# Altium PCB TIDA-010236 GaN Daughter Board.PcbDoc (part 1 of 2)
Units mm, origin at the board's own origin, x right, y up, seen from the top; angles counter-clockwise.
Board outline 68 x 45 mm, 4 copper layers (Top Layer, Signal Layer 1, Signal Layer 2, Bottom Layer), stack 1.57 mm thick; 74 components, 38 nets, 269 pads, 167 vias.
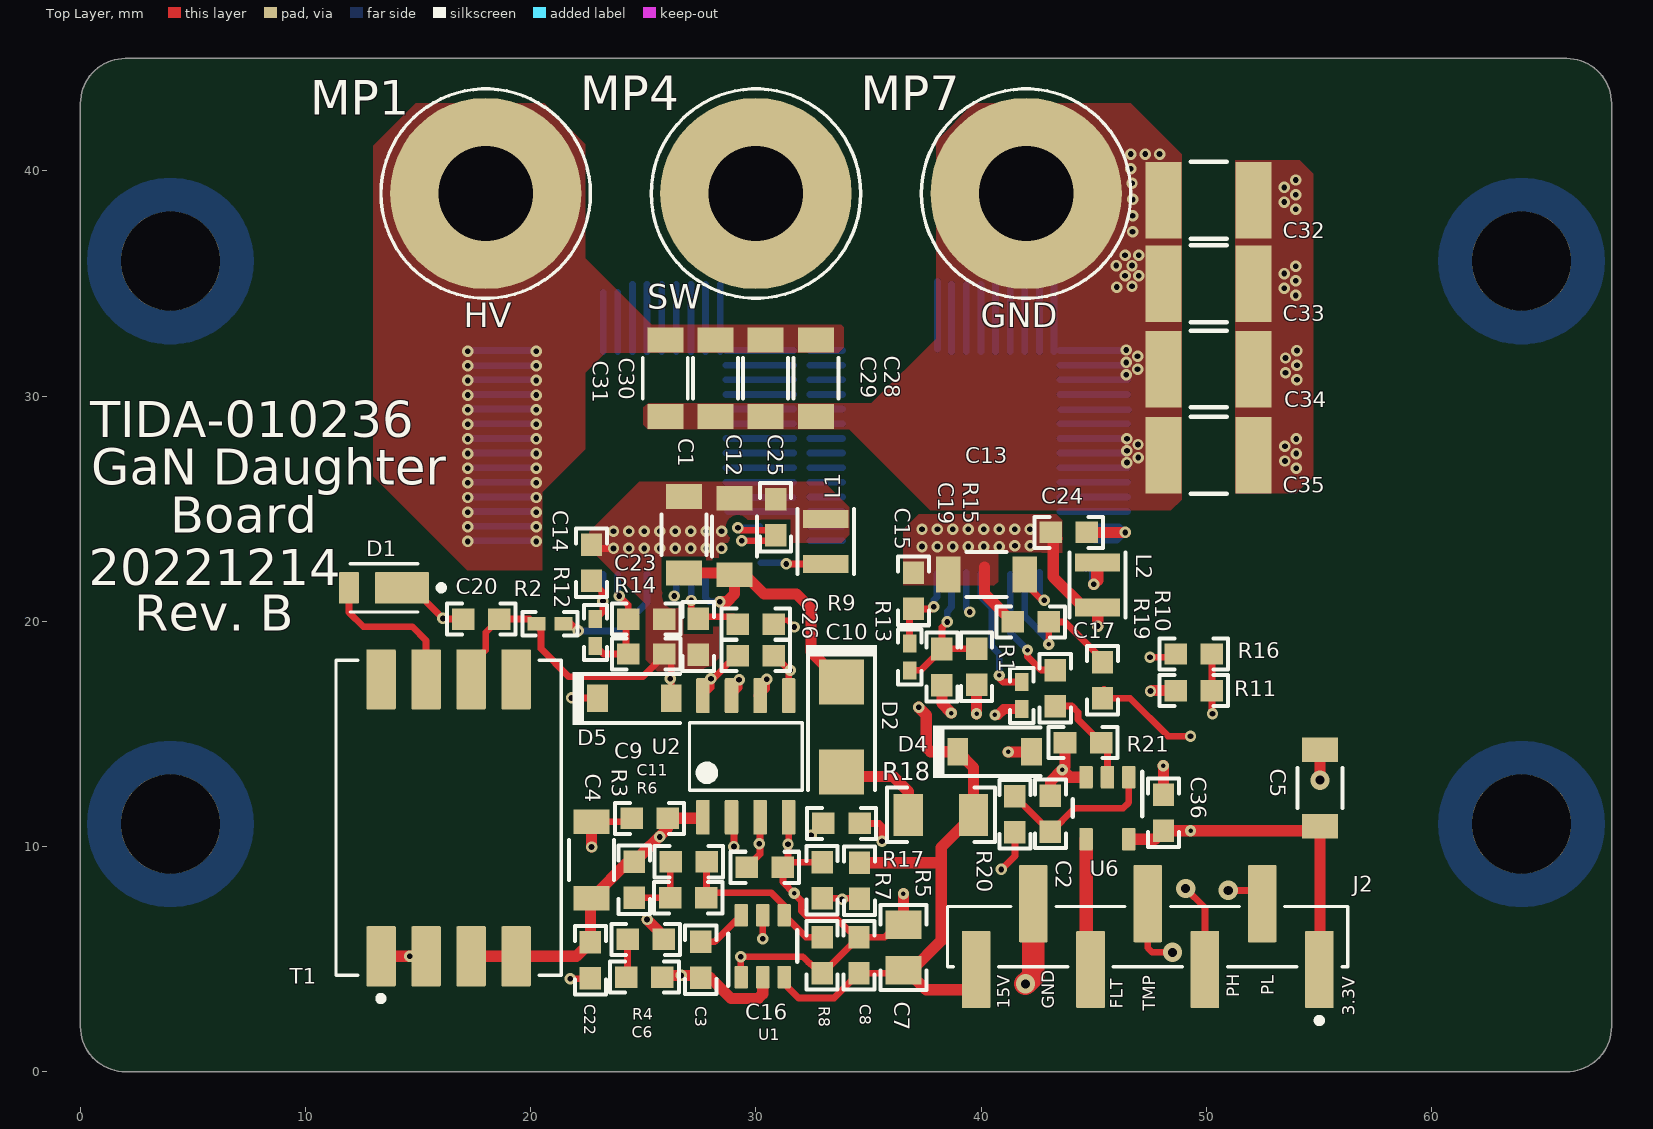
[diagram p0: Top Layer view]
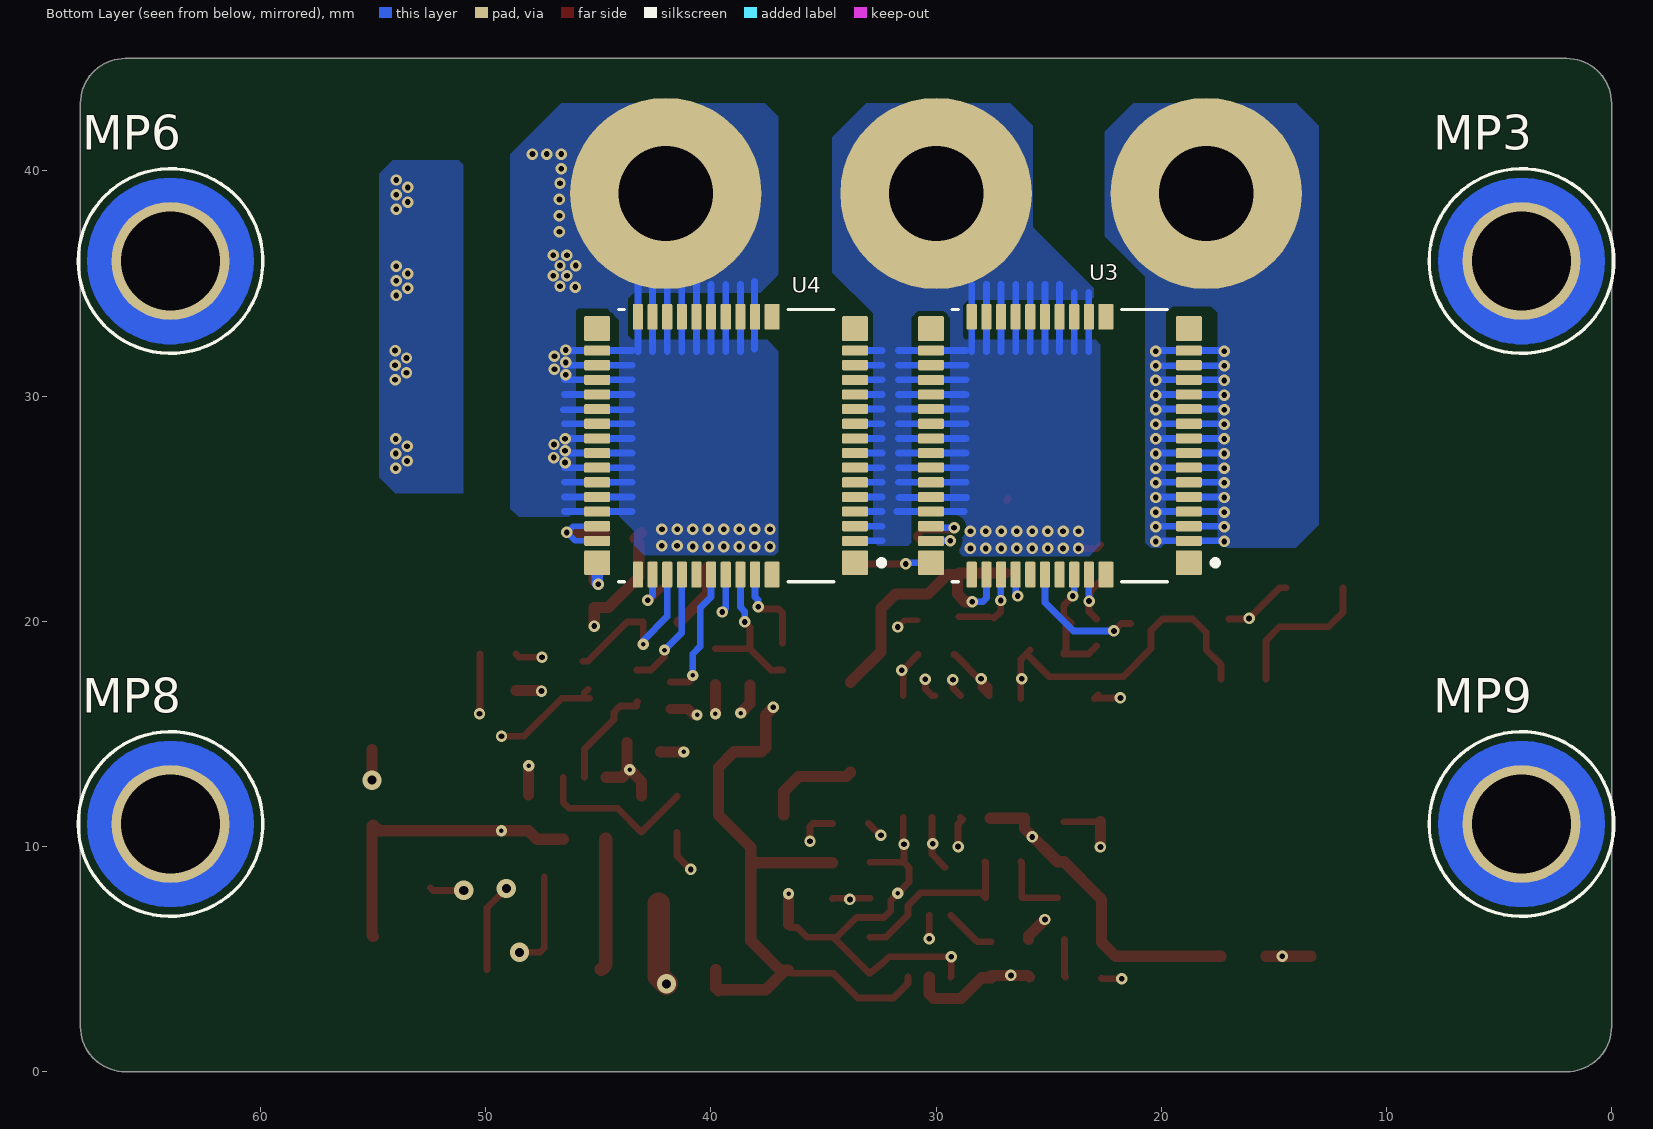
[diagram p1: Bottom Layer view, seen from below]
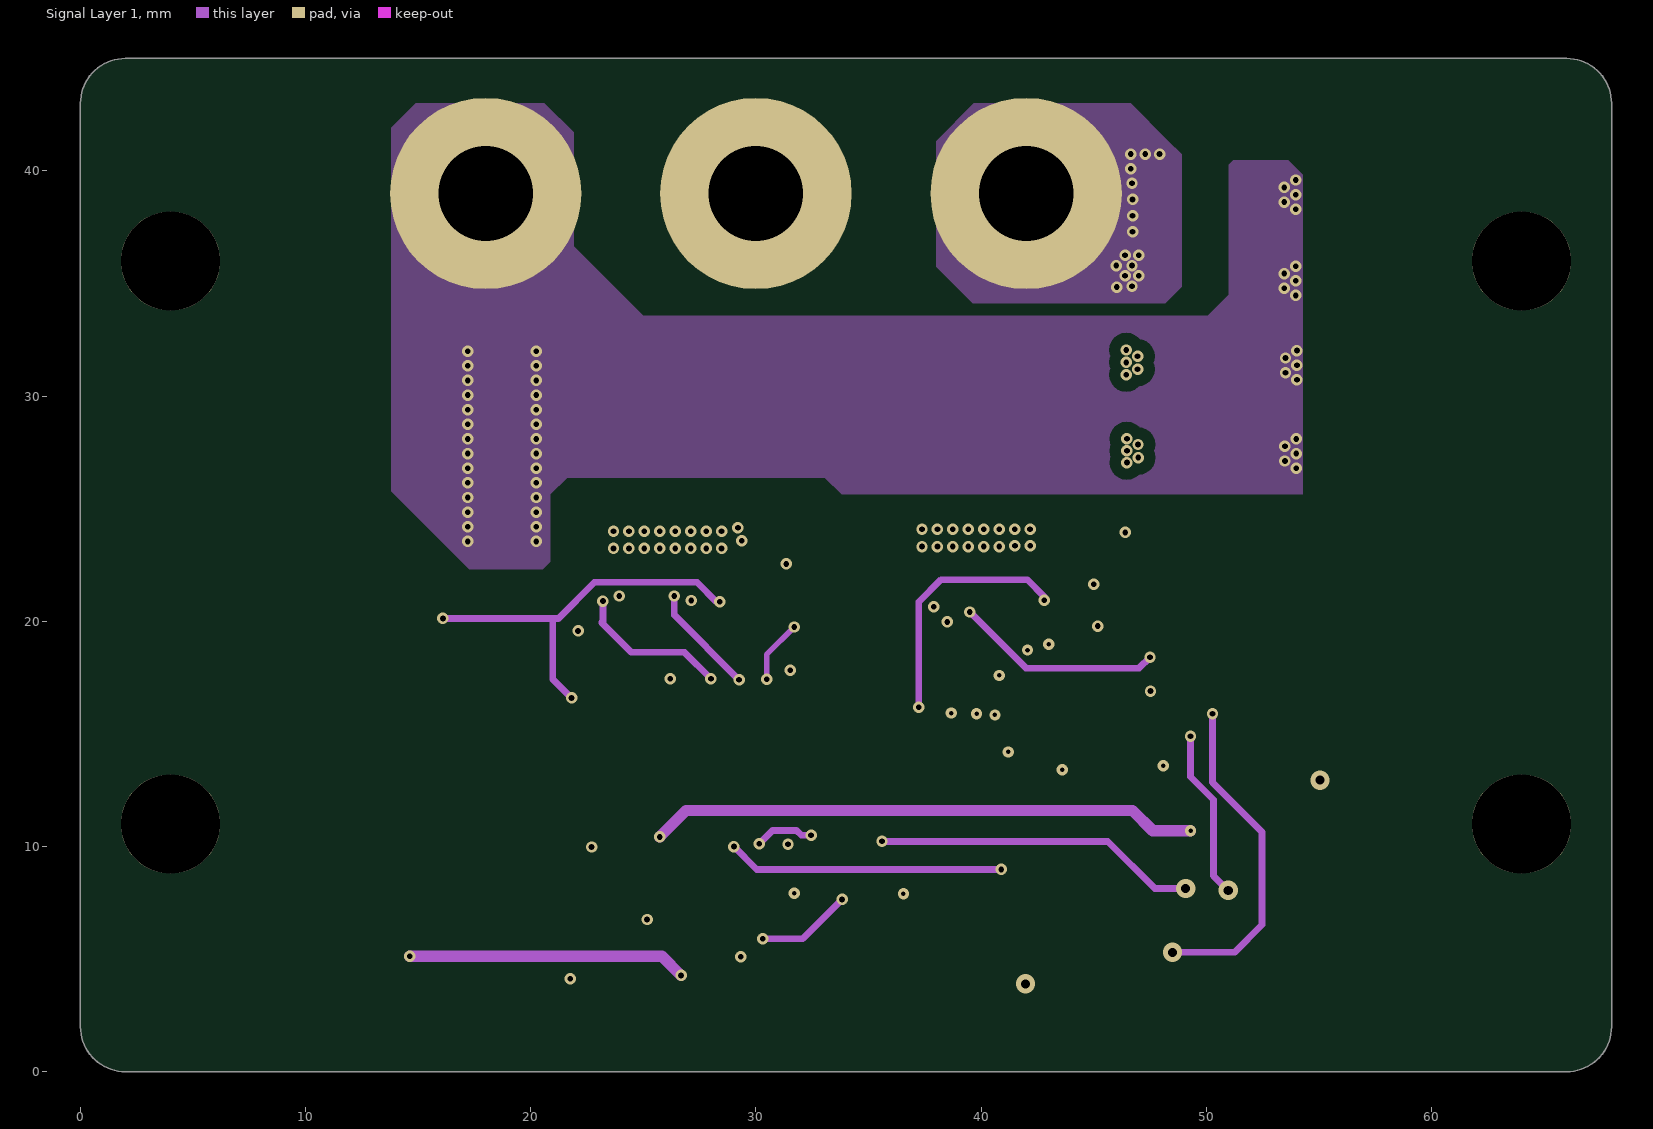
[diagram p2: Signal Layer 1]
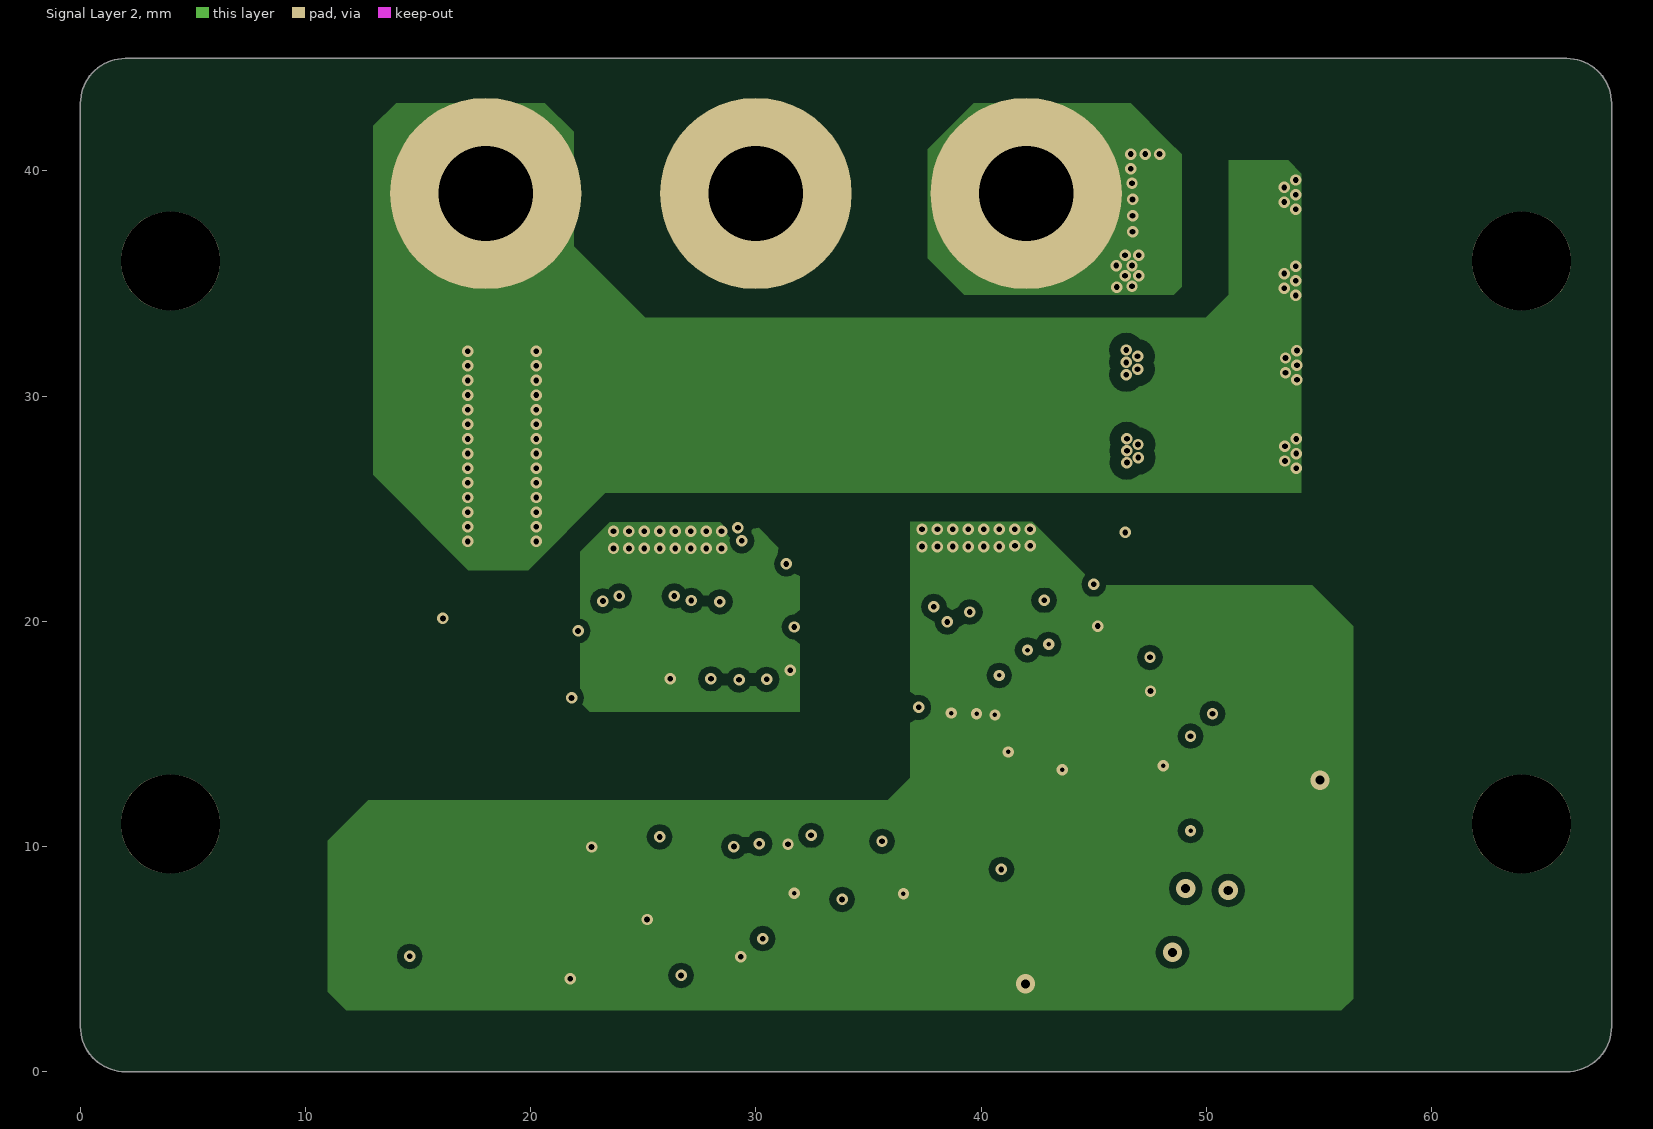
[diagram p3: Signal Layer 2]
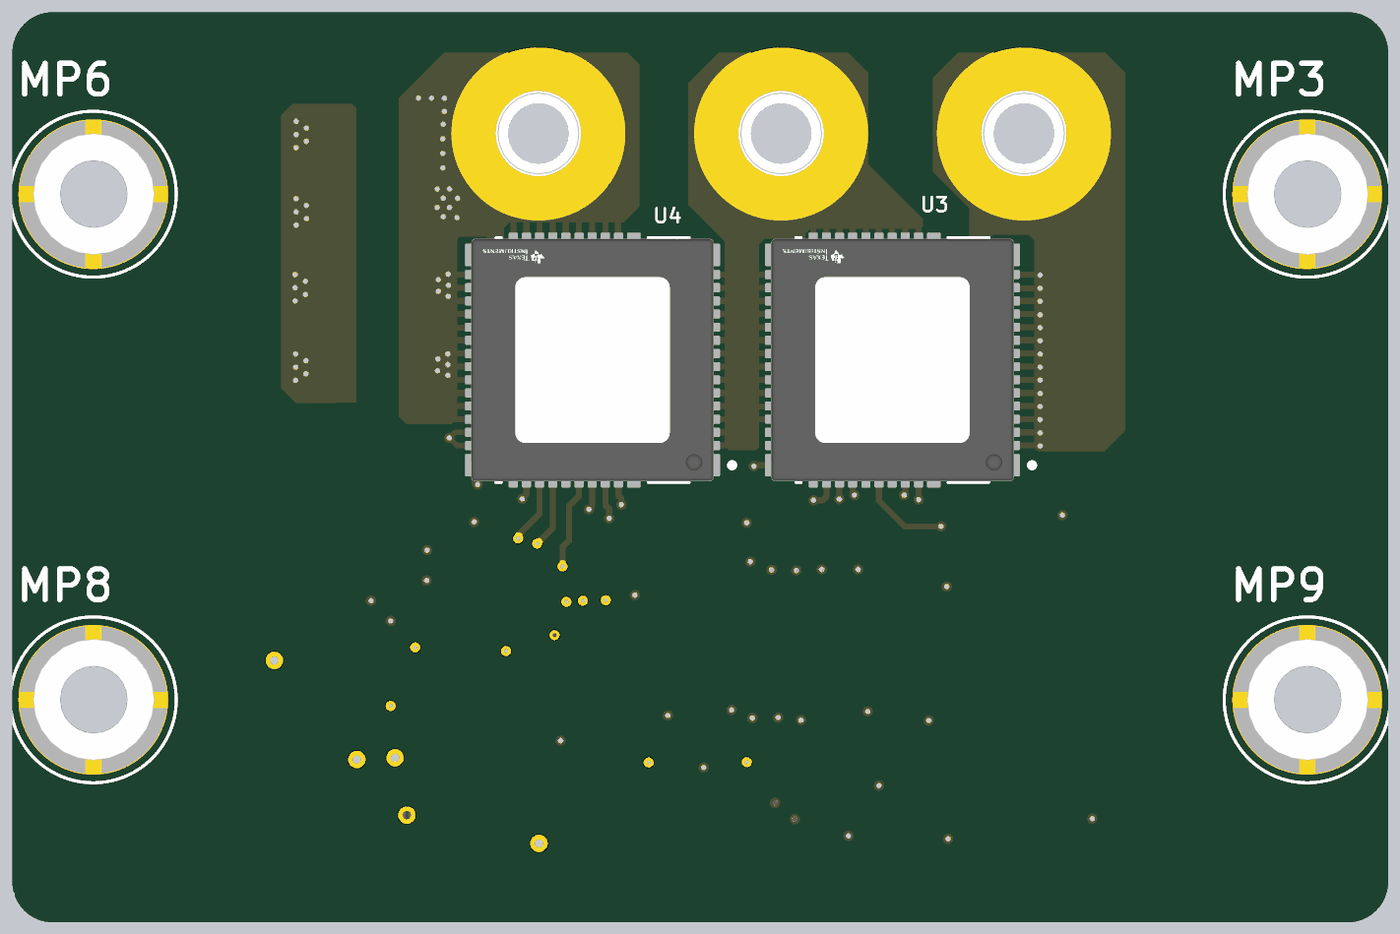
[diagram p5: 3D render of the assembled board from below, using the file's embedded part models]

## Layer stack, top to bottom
Top Solder: solder mask 0.0102, Solder Resist, Dk 3.5
Top Layer: signal copper 0.07
Dielectric 2: prepreg 0.43, Dk 4.2
Signal Layer 1: signal copper 0.07
Dielectric 3: core 0.43, Dk 4.2
Signal Layer 2: signal copper 0.07
Dielectric1: prepreg 0.43, FR-4, Dk 4.2
Bottom Layer: signal copper 0.07
Bottom Solder: solder mask 0.0102, Solder Resist, Dk 3.5

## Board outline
0,2 0,43 cw(c2,43) 2,45 66,45 cw(c66,43) 68,43 68,2 cw(c66,2) 66,0 2,0 cw(c2,2)

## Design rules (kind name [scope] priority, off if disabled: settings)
AcuteAngle [All] p1: minimum=4.50000000000000E+0001 checktracksonly=FALSE
AssemblyTestPointUsage [All] p1: valid=2
BoardOutlineClearance BoardOutlineClearance_MountingHoles [OnCopper and InComponentClass('Mounting Holes')] p1: gap=1 ignorepadtopadclearanceinfootprint=FALSE
BoardOutlineClearance BoardOutlineClearance_Poly [OnCopper and IsPoly] p2: gap=0.635 ignorepadtopadclearanceinfootprint=FALSE
BoardOutlineClearance [OnCopper and Not InComponentClass('Logo') and not InComponentClass('FiducialMark') and not InRegion(1000,500,4000,800) and not InPoly] p3: gap=1 ignorepadtopadclearanceinfootprint=FALSE
Clearance HVBUS_GND [InNet('HV_BUS') vs InNet('GND')] p1: gap=0.5 ignorepadtopadclearanceinfootprint=TRUE
Clearance SW_GND [InNet('SW') vs InNet('GND')] p2: gap=0.5 ignorepadtopadclearanceinfootprint=TRUE
Clearance HVBUS_SW [InNet('HV_BUS') vs InNet('SW')] p3: gap=0.5 ignorepadtopadclearanceinfootprint=TRUE
Clearance Clearance_Keepouts [((IsTrack Or IsArc) And Not InPoly) And IsFree and IsKeepOut vs ((IsTrack Or IsArc) And Not InPoly) And IsFree and IsKeepOut] p4: gap=0 ignorepadtopadclearanceinfootprint=FALSE
Clearance Clearance_Poly [InPolygon] p5: gap=0.3 ignorepadtopadclearanceinfootprint=TRUE except(0.2: SMDPad-Fill SMDPad-Poly SMDPad-Region)
Clearance Clearance_FiducialMark [IsKeepOut and InComponentClass('FiducialMark') vs IsPad and InComponentClass('FiducialMark')] p6: gap=0 ignorepadtopadclearanceinfootprint=FALSE
Clearance [All] p7: gap=0.2 ignorepadtopadclearanceinfootprint=TRUE
ComponentClearance ComponentClearance_MountingHoles_FiducialMarks [InComponentClass('Mounting Holes') vs InComponentClass('FiducialMark')] p1 off: gap=1.27 collisioncheckmode=3 verticalgap=0.254 showdistances=FALSE
ComponentClearance ComponentClearance_Shunt [InComponentClass('Header') vs InComponentClass('Shunt')] p2 off: gap=0 collisioncheckmode=3 verticalgap=0 showdistances=FALSE
ComponentClearance ComponentClearance_Logo [InComponentClass('Logo')] p3 off: gap=1.27 collisioncheckmode=3 verticalgap=0.254 showdistances=FALSE
ComponentClearance ComponentClearance_ScrewToNut [(HasFootprint('NY PMS 440 0025 PH')) vs (HasFootprint('Keystone_1902C'))] p4 off: gap=0.127 collisioncheckmode=3 verticalgap=0.254 showdistances=FALSE
ComponentClearance ComponentClearance_MountingHoles [InComponentClass('Mounting Holes')] p5 off: gap=6.35 collisioncheckmode=3 verticalgap=2540 showdistances=FALSE
ComponentClearance ComponentClearance_SmallPassives [HasFootprint('0201*') or HasFootprint('0402*') or HasFootprint('0508') or HasFootprint('0603*') or HasFootprint('0612') or HasFootprint('0805*') or HasFootprint('0815*') or HasFootprint('0830*') or HasFootprint('1206*') or HasFootprint('1210*') or HasFootprint('1808*') or HasFootprint('1812*') or HasFootprint('1825*') or HasFootprint('2010*') or HasFootprint('2220*') or HasFootprint('2225*') or HasFootprint('2512*') or HasFootprint('2728*') or HasFootprint('3518*') vs HasFootprint('0201*') or HasFootprint('0402*') or HasFootprint('0508') or HasFootprint('0603*') or HasFootprint('0612') or HasFootprint('0805*') or HasFootprint('0815*') or HasFootprint('0830*') or HasFootprint('1206*') or HasFootprint('1210*') or HasFootprint('1808*') or HasFootprint('1812*') or HasFootprint('1825*') or HasFootprint('2010*') or HasFootprint('2220*') or HasFootprint('2225*') or HasFootprint('2512*') or HasFootprint('2728*') or HasFootprint('3518*')] p6 off: gap=0.38 collisioncheckmode=3 verticalgap=0.254 showdistances=FALSE
ComponentClearance ComponentClearance_THtoSMT [IsThruComponent vs IsSMTComponent] p7 off: gap=1.016 collisioncheckmode=3 verticalgap=0.762 showdistances=FALSE
ComponentClearance ComponentClearance_THtoTH [IsThruComponent vs IsThruComponent] p8 off: gap=0.762 collisioncheckmode=3 verticalgap=0.762 showdistances=FALSE
ComponentClearance [All] p9 off: gap=0.762 collisioncheckmode=3 verticalgap=0.254 showdistances=FALSE
DiffPairsRouting [All] p1: maxlimit=2.54 minlimit=0.254 mostfreqgap=0.254 toplayer_minwidth=0.381 toplayer_maxwidth=0.381 toplayer_prefwidth=0.381 midlayer1_minwidth=0.381 midlayer1_maxwidth=0.381 midlayer1_prefwidth=0.381 midlayer2_minwidth=0.381 midlayer2_maxwidth=0.381 midlayer2_prefwidth=0.381 bottomlayer_minwidth=0.381 bottomlayer_maxwidth=0.381 bottomlayer_prefwidth=0.381 maxuncoupledlength=25.4
FabricationTestPointUsage TestPointUsage [All] p1: valid=2 allowmultiple=FALSE
FabricationTestpoint Testpoint [All] p1: side=3 testpointundercomponent=TRUE minsize=1.016 maxsize=2.54 preferedsize=1.524 minholesize=0 maxholesize=1.016 preferedholesize=0.813 testpointgrid=0.025 allowsidetop=TRUE allowsidebottom=TRUE usegrid=TRUE gridtolerance=0
FanoutControl Fanout_LCC [IsLCC] p1: bgadir=Out bgaviamode=Centered fanoutstyle=Auto fanoutdirection=Alternating viagrid=0.025 // Fanout_LCC (Default Rule)
FanoutControl Fanout_BGA [IsBGA] p2: bgadir=Out bgaviamode=Centered fanoutstyle=Auto fanoutdirection=Alternating viagrid=0.025 // Fanout_BGA (Default Rule)
FanoutControl Fanout_Default [All] p4: bgadir=Out bgaviamode=Centered fanoutstyle=Auto fanoutdirection=Alternating viagrid=0.025 // Fanout_Default (Default Rule)
FanoutControl Fanout_Small [(CompPinCount < 5)] p5: bgadir=Out bgaviamode=Centered fanoutstyle=Auto fanoutdirection=OutThenIn viagrid=0.025 // Fanout_Small (Default Rule)
Height [All] p1 off: minheight=0 maxheight=25.4 prefheight=12.7
HoleSize [All] p1: absolutevalues=TRUE maxlimit=6.375 minlimit=0.2 maxpercent=80.000 minpercent=20.000
MinimumAnnularRing MinimumAnnularRing_ThermalPadVias [IsVia and InAnyComponent] p1: minimumring=0.15
MinimumAnnularRing [All] p2: minimumring=0.1
MinimumSolderMaskSliver MinimumSolderMaskSliver_Logo [InComponentClass('Logo') vs InComponentClass('Logo')] p1: minsoldermaskwidth=0.018
MinimumSolderMaskSliver [All] p2: minsoldermaskwidth=0.1
PlaneClearance [All] p1: clearance=0.3
PlaneConnect [All] p1: planeconnectstyle=Relief reliefexpansion=0.254 reliefentries=4 reliefconductorwidth=0.254 reliefairgap=0.254
PolygonConnect [All] p1: connectstyle=Direct reliefconductorwidth=0.254 reliefentries=4 polygonreliefangle="90 Angle" airgapwidth=0.254
RoutingVias ThermalPadVias [IsVia and InAnyComponent] p1: holewidth=0.2 width=0.5 viastyle="Through Hole" minholewidth=0.2 minwidth=0.5 maxholewidth=0.33 maxwidth=0.6
RoutingVias [All] p2: holewidth=0.2 width=0.5 viastyle="Through Hole" minholewidth=0.2 minwidth=0.4 maxholewidth=1.016 maxwidth=1.651
SilkToBoardRegionClearance [Not ((IsComment or IsDesignator) And (Hide <> 'False')) and not InRegion(1000,500,4000,800)] p1:
SilkToSilkClearance SilkToSilkClearance_Pb-FreeLogo [(HasFootprint('Pb-Free_Overlay_Medium') OR HasFootprint('Pb-Free_Overlay_Small')) vs (HasFootprint('Pb-Free_Overlay_Medium') OR HasFootprint('Pb-Free_Overlay_Small'))] p1: silktosilkclearance=0
SilkToSilkClearance [All] p2: silktosilkclearance=0.1
SilkToSolderMaskClearance SilkToComponentPadClearance [(IsPad or IsFill or IsRegion) and InAnycomponent] p1: minsilkscreentomaskgap=0.127 clearancetoexposedcopper=TRUE
SilkToSolderMaskClearance "Silk to Solder Mask Opening" [All] p2: minsilkscreentomaskgap=0.1 clearancetoexposedcopper=FALSE
SolderMaskExpansion [All] p1: expansion=0.05 istentingtop=FALSE
UnRoutedNet [All] p1: checkbadconnections=TRUE
Width [All] p1: maxlimit=2.54 minlimit=0.152 preferedwidth=0.254 checkconnectedcopper=TRUE
12 further rules are at their usual default settings.

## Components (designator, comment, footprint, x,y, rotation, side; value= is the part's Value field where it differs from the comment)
C1 "C3216X7R1V106M160AC" 1206_190 26.8,23.85 r90 top value=10uF
C2 "GRM1885C1H470JA01D" 0603 43.077,11.45 r90 top value=47pF
C3 "06035C104JAT2A" 0603 27.55,4.975 r90 top value=0.1uF
C4 "GRM31CR71A226ME15L" 1206_180 22.7,9.4 r90 top value=22uF
C5 "GRM31CR71A226ME15L" 1206_180 55.05,12.6 r90 top value=22uF
C6 "GRM1885C1H101JA01D" 0603 25.05,4.2 r0 top value=100pF
C7 "CGA4J1X7R1V335K125AC" 0805_HV 36.55,5.516 r90 top value=3.3uF
C8 "06035C104JAT2A" 0603 34.575,5.175 r90 top value=0.1uF
C9 "06035C104JAT2A" 0603 25.275,11.25 r180 top value=0.1uF
C10 "06035C104JAT2A" 0603 30,18.475 r0 top value=0.1uF
C11 "GRM1885C1H750JA01D" 0603 27.025,9.323 r0 top value=75pF
C12 "C3216X7R1V106M160AC" 1206_190 29.05,23.767 r90 top value=10uF
C13 "C3216X7R1V106M160AC" 1206_190 40.24,22.075 r180 top value=10uF
C14 "GRM188R71E224KA88D" 0603 22.7,22.6 r270 top value=0.22uF
C15 "GRM188R71E224KA88D" 0603 37,21.35 r270 top value=0.22uF
C16 "C0603C331K5RACTU" 0603 30.4,9.075 r0 top value=330pF
C17 "GRM188R71H221KA01D" 0603 42.2,19.974 r180 top value=220pF
C19 "GRM1885C1H101JA01D" 0603 38.26,17.972 r270 top value=100pF
C20 "06035C104JAT2A" 0603 17.8,20.1 r0 top value=0.1uF
C22 "06035C104JAT2A" 0603 22.65,4.95 r270 top value=0.1uF
C23 "GRM1885C1H101JA01D" 0603 25.125,20.1 r0 top value=100pF
C24 "GRM188R6YA225KA12D" 0603 43.9,23.95 r180 top value=2.2uF
C25 "GRM188R6YA225KA12D" 0603 30.875,24.625 r90 top value=2.2uF
C26 "GCM1885C1H680JA16D" 0603 27.44,19.325 r270 top value=68pF
C28 "C1206C223KDRACTU" 1206_190 32.666,30.8 r270 top value=0.022uF
C29 "C1206C223KDRACTU" 1206_190 30.422,30.8 r270 top value=0.022uF
C30 "C1206C223KDRACTU" 1206_190 28.2,30.8 r270 top value=0.022uF
C31 "C1206C223KDRACTU" 1206_190 25.976,30.8 r270 top value=0.022uF
C32 "C1812W104KDRACTU" 1812_254 50.1,38.7 r180 top value=0.1uF
C33 "C1812W104KDRACTU" 1812_254 50.1,34.992 r180 top value=0.1uF
C34 "C1812W104KDRACTU" 1812_254 50.1,31.2 r180 top value=0.1uF
C35 "C1812W104KDRACTU" 1812_254 50.1,27.375 r180 top value=0.1uF
C36 "06035C104JAT2A" 0603 48.1,11.5 r90 top value=0.1uF
D1 "SS1H20LS RVG" "FP-SS1H20LS RVG_SOD123HE-MFG" 13.475,21.49 r180 top
D2 "US1M-13-F" SMA 33.8,15.3 r270 top value=1000V
D4 "BZT52C18-7-F" SOD-123 40.6,14.212 r0 top value=18V
D5 "BZT52C18-7-F" SOD-123 24.6,16.575 r0 top value=18V
J2 "TSM-107-03-L-SV" FP-TSM-107-03-L-SV_HDR7-MFG 47.4,6 r180 top locked
L1 "1269AS-H-4R7M=P2" DFE252010C 33.1,23.55 r270 top value=4.7uH
L2 "1269AS-H-4R7M=P2" DFE252010C 45.175,21.615 r90 top value=4.7uH
MP1 "74660036" FP-74660036_SMT_BUSH-MFG 18,39 r0 top
MP3 "9774010960" FP-9774010960_SPACER_ROUND-MFG 4,36 r180 bottom
MP4 "74660036" FP-74660036_SMT_BUSH-MFG 30,39 r0 top
MP6 "9774010960" FP-9774010960_SPACER_ROUND-MFG 64,36 r180 bottom
MP7 "74660036" FP-74660036_SMT_BUSH-MFG 42,39 r0 top
MP8 "9774010960" FP-9774010960_SPACER_ROUND-MFG 64,11 r180 bottom
MP9 "9774010960" FP-9774010960_SPACER_ROUND-MFG 4,11 r180 bottom
R1 "RC0402JR-070RL" 0402 41.8,16.701 r90 top value=0
R2 "RC0402JR-070RL" 0402 20.85,19.9 r0 top value=0
R3 "RC0603FR-0751RL" 0603 24.594,8.525 r90 top value=51.0
R4 "RC0603FR-07100RL" 0603 25.1,5.875 r0 top value=100
R5 "RC0603FR-07511KL" 0603 34.6,8.475 r90 top value=511k
R6 "RC0603FR-07100KL" 0603 27,7.725 r180 top value=100k
R7 "RC0603FR-07100KL" 0603 32.94,8.5 r270 top value=100k
R8 "RC0603FR-0722K1L" 0603 32.94,5.175 r90 top value=22.1k
R9 "RC0603FR-07300RL" 0603 30,19.875 r0 top value=300
R10 "RC0603FR-07300RL" 0603 45.389,17.385 r270 top value=300
R11 "RC0603FR-072KL" 0603 49.45,16.925 r180 top value=2.00k
R12 "RC0402JR-070RL" 0402 22.875,19.5 r270 top value=0
R13 "RC0402JR-070RL" 0402 36.825,18.425 r270 top value=0
R14 "RC0603FR-0720KL" 0603 25.125,18.55 r180 top value=20.0k
R15 "RC0603FR-0720KL" 0603 39.799,17.985 r90 top value=20.0k
R16 "RC0603FR-071KL" 0603 49.45,18.55 r180 top value=1.00k
R17 "RC0603FR-0751RL" 0603 33.8,11.025 r180 top value=51.0
R18 "RC1206FR-0710RL" 1206 38.215,11.4 r180 top value=10.0
R19 "RC0603FR-071KL" 0603 43.293,17.035 r270 top value=1.00k
R20 "RC0603FR-07300RL" 0603 41.5,11.428 r90 top value=300
R21 "RC0603FR-072KL" 0603 44.526,14.613 r0 top value=2.00k
T1 "750344971" FP-750344971_SMT_XFRMR_14MM0_10MM0-MFG 16.35,11.275 r90 top
U1 "TPS54308DDCR" DDC0006A_N 30.3,5.575 r90 top
U2 "ISO7721FDR" D0008A-MFG 29.55,14 r90 top
U3 "LMG3522R030-Q1" RQS0052C-C01-MFG 24.5,27.8 r0 bottom locked
U4 "LMG3522R030-Q1" RQS0052C-C01-MFG 39.325,27.8 r0 bottom locked
U6 "SN74AHC1G08DBVR" DBV0005A_N 45.611,11.7 r270 top

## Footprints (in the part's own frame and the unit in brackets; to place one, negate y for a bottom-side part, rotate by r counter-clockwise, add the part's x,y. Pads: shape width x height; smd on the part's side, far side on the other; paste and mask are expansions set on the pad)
0402 [mm] "0402 from SM-752 data"
  rect 0.8x0.6 smd: 1(-0.6,0) 2(0.6,0)
  silkscreen extent -1.22,-0.52 1.22,0.52, body extent -0.55,-0.3 0.55,0.3, height 0.6
0603 [mm] "0603 from SM-752 data"
  rect 1x0.95 smd: 1(-0.8,0) 2(0.8,0)
  silkscreen extent -1.52,-0.69 1.52,0.69, body extent -0.87,-0.47 0.87,0.47, height 1
0805_HV [mil] "0805 with 30mil clearance between pads"
  rect 50x63 smd: 1(-40,0) 2(40,0)
  silkscreen extent -74,-40 74,40, body extent -43,-29 43,29, height 57
1206 [mm] "1206 from SM-752 data"
  rect 1.3x1.85 smd: 1(-1.45,0) 2(1.45,0)
  silkscreen extent -2.4,-1.21 2.4,1.21, body extent -1.7,-0.9 1.7,0.9, height 1.35
1206_180 [mm] "1206_180"
  rect 1.1x1.6 smd: 1(-1.7,0) 2(1.7,0)
  silkscreen extent -0.9,-1 0.9,1, body extent -1.75,-0.95 1.75,0.95, height 1.8
1206_190 [mm] "1206_190"
  rect 1.1x1.6 smd: 1(-1.7,0) 2(1.7,0)
  silkscreen extent -0.9,-1 0.9,1, body extent -1.75,-0.95 1.75,0.95, height 1.9
1812_254 [mm] "SMD, 2-Leads, Body 4.8x3.4mm"
  rect 1.6x3.4 smd: 1(-2,0) 2(2,0)
  silkscreen extent -0.8,-1.7 0.8,1.7, body extent -2.4,-1.7 2.4,1.7, height 2.54
D0008A-MFG [mm]
  rrect17% 1.55x0.6 smd paste+0 mask+0: 1(-2.7,1.905) 2(-2.7,0.635) 3(-2.7,-0.635) 4(-2.7,-1.905) 5(2.7,-1.905) 6(2.7,-0.635) 7(2.7,0.635) 8(2.7,1.905)
  silkscreen extent -1.5,-2.5 1.5,2.5, body extent -3.57,-2.75 3.57,2.75, height 0.25
DBV0005A_N [mm] "SOT23, 5-Leads, Body 2.9x1.6mm, Pitch 0.95mm, Lead Span 2.8mm, IPC Medium Density"
  rrect17% 1x0.6 smd: 1(-1.375,0.95) 2(-1.375,0) 3(-1.375,-0.95) 4(1.375,-0.95) 5(1.375,0.95)
  silkscreen extent -1.63,-1.55 0.38,1.55, body extent -1.42,-1.46 1.42,1.46, height 1.09
DDC0006A_N [mm]
  rrect17% 1x0.6 smd: 1(-1.375,0.95) 2(-1.375,0) 3(-1.375,-0.95) 4(1.375,-0.95) 5(1.375,0) 6(1.375,0.95)
  silkscreen extent -1.75,-1.52 0.7,1.53, body extent -1.43,-1.48 1.43,1.49, height 0.92
DFE252010C [mm] "Toko"
  rect 0.8x2 smd: 1(-1,0) 2(1,0)
  silkscreen extent -1.45,-1.25 1.45,1.25, body extent -1.35,-1.1 1.35,1.1, height 1.2
FP-74660036_SMT_BUSH-MFG [mm]
  round 8.5 hole 4.2 paste-1000: 1(0,0)
  silkscreen extent -4.65,-4.65 4.65,4.65, body extent -4.35,-4.35 4.35,4.35, height 0.25
FP-750344971_SMT_XFRMR_14MM0_10MM0-MFG [mm]
  rrect8% 2.67x1.31 smd paste+0 mask+0: 1(-6.15,3) 2(-6.15,1) 3(-6.15,-1) 4(-6.15,-3) 5(6.15,-3) 6(6.15,-1) 7(6.15,1) 8(6.15,3)
  silkscreen extent -8.15,-5 7,5, body extent -7.58,-5.1 7.58,5.1, height 0.25
FP-9774010960_SPACER_ROUND-MFG [mm]
  round 5.245 smd paste-1000 mask-1000: 1(0,0)
  round 4.4 hole 4.4 unplated paste-1000 mask+0: ""(0,0)
  Top Layer circle w1.5: c0,0 r2.95
  silkscreen extent -4.1,-4.1 4.1,4.1, body extent -2.98,-2.99 3.02,3.01, height 1.1
"FP-SS1H20LS RVG_SOD123HE-MFG" [mm]
  rrect7% 2.4x1.4 smd paste+0 mask+0: 1(-0.8,0)
  rrect11% 0.9x1.4 smd paste+0 mask+0: 2(1.55,0)
  silkscreen extent -2.68,-1.07 1.5,1.07, body extent -2.1,-1.07 2.1,1.07, height 0.25
FP-TSM-107-03-L-SV_HDR7-MFG [mm]
  rrect8% 1.27x3.43 smd paste+0 mask+0: 1(-7.62,1.46) 2(-5.08,-1.46) 3(-2.54,1.46) 4(0,-1.46) 5(2.54,1.46) 6(5.08,-1.46) 7(7.62,1.46)
  silkscreen extent -8.89,-1.34 8.89,3.85, body extent -8.99,-3.27 8.99,3.27, height 0.25
RQS0052C-C01-MFG [mm]
  rrect9% 1.15x1.1 smd paste+0 mask+0: 1(-5.725,5.2) 16(-5.725,-5.2) 27(5.725,-5.2) 42(5.725,5.2)
  rrect22% 1.15x0.45 smd paste+0 mask+0: 2(-5.725,4.225) 3(-5.725,3.575) 4(-5.725,2.925) 5(-5.725,2.275) 6(-5.725,1.625) 7(-5.725,0.975) 8(-5.725,0.325) 9(-5.725,-0.325) 10(-5.725,-0.975) 11(-5.725,-1.625) 12(-5.725,-2.275) 13(-5.725,-2.925) 14(-5.725,-3.575) 15(-5.725,-4.225) 28(5.725,-4.225) 29(5.725,-3.575) 30(5.725,-2.925) 31(5.725,-2.275) 32(5.725,-1.625) 33(5.725,-0.975) 34(5.725,-0.325) 35(5.725,0.325) 36(5.725,0.975) 37(5.725,1.625) 38(5.725,2.275) 39(5.725,2.925) 40(5.725,3.575) 41(5.725,4.225)
  rrect15% 0.665x1.15 smd paste+0 mask+0: 17(-2.043,-5.725) 52(-2.043,5.725)
  rrect22% 0.45x1.15 smd paste+0 mask+0: 18(-1.285,-5.725) 19(-0.635,-5.725) 20(0.015,-5.725) 21(0.665,-5.725) 22(1.315,-5.725) 23(1.965,-5.725) 24(2.615,-5.725) 25(3.265,-5.725) 26(3.915,-5.725) 43(3.915,5.725) 44(3.265,5.725) 45(2.615,5.725) 46(1.965,5.725) 47(1.315,5.725) 48(0.665,5.725) 49(0.015,5.725) 50(-0.635,5.725) 51(-1.285,5.725)
  silkscreen extent -7.02,-6.05 4.77,6.05, body extent -6,-6 6,6, height 1
SMA [mm] "Molded Diode, 2-Leads, Body 4.3x2.6mm, IPC Medium Density, based on OnSemi component dimensions and land pattern"
  rect 2x2 smd: 1(-2,0) 2(2,0)
  silkscreen extent -3.66,-1.57 2.79,1.57, body extent -2.6,-1.3 2.6,1.3, height 2.42
SOD-123 [mm] "On Semi recommended land pattern"
  rect 0.915x1.22 smd: 1(-1.637,0) 2(1.637,0)
  silkscreen extent -2.74,-1.17 2.03,1.17, body extent -1.93,-0.9 1.93,0.9, height 1.35

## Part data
C1 C12 C13: library part CMP-0008706-2, "CAP, CERM, 10 uF, 35 V, +/- 20%, X7R, 1206_190", Cap_Case=1206, Manufacturer=TDK, Supplier Part Number 1=445-8034-1-ND, TempCo=X7R, Tolerance_%=20%, Value1=Unknown, Value2=35V, ValueDisplayed=10uF
C2: library part CMP-0007220-2, "CAP, CERM, 47 pF, 50 V, +/- 5%, C0G/NP0, 0603", Cap_Case=0603, Manufacturer=MuRata, Supplier Part Number 1=490-1419-1-ND, TempCo=C0G/NP0, Tolerance_%=5%, Value1=Unknown, Value2=50V, ValueDisplayed=47pF
C3 C8 C9 C10 C20 C22 C36: library part CMP-0083854-1, "CAP, CERM, 0.1 µF, 50 V,+/- 5%, X7R, 0603", Cap_Case=0603, Manufacturer=AVX, TempCo=X7R, Tolerance_%=5%, Value2=50V, ValueDisplayed=0.1µF
C4 C5: library part CMP-0008960-1, "CAP, CERM, 22 uF, 10 V, +/- 20%, X7R, 1206", Cap_Case=1206, Manufacturer=MuRata, Supplier Part Number 1=490-6516-1-ND, TempCo=X7R, Tolerance_%=20%, Value1=Unknown, Value2=10V, ValueDisplayed=22uF
C6 C19 C23: library part CMP-0007171-4, "CAP, CERM, 100 pF, 50 V, +/- 5%, C0G/NP0, 0603", Cap_Case=0603, Manufacturer=MuRata, Supplier Part Number 1=490-1427-1-ND, TempCo=C0G/NP0, Tolerance_%=5%, Value1=Unknown, Value2=50V, ValueDisplayed=100pF
C7: library part CMP-0007963-2, "CAP, CERM, 3.3 uF, 35 V, +/- 10%, X7R, AEC-Q200 Grade 1, 0805", Cap_Case=0805, Manufacturer=TDK, Supplier Part Number 1=810-CGA4J1X7R1V335K125AC, TempCo=X7R, Tolerance_%=10%, Value1="0.002798 ohm", Value2=35V, ValueDisplayed=3.3uF
C11: library part CMP-0007230-4, "CAP, CERM, 75 pF, 50 V, +/- 5%, C0G/NP0, 0603", Cap_Case=0603, Manufacturer=MuRata, Supplier Part Number 1=490-1424-1-ND, TempCo=C0G/NP0, Tolerance_%=5%, Value1=Unknown, Value2=50V, ValueDisplayed=75pF
C14 C15: library part CMP-0007415-1, "CAP, CERM, 0.22 uF, 25 V, +/- 10%, X7R, 0603", Cap_Case=0603, Manufacturer=MuRata, Supplier Part Number 1=490-3290-1-ND, TempCo=X7R, Tolerance_%=10%, Value1=Unknown, Value2=25V, ValueDisplayed=0.22uF
C16: library part CMP-0006921-4, "CAP, CERM, 330 pF, 50 V, +/- 10%, X7R, 0603", Cap_Case=0603, Manufacturer=Kemet, Supplier Part Number 1=399-1073-1-ND, TempCo=X7R, Tolerance_%=10%, Value1=Unknown, Value2=50V, ValueDisplayed=330pF
C17: library part CMP-0007442-3, "CAP, CERM, 220 pF, 50 V, +/- 10%, X7R, 0603", Cap_Case=0603, Manufacturer=MuRata, Supplier Part Number 1=490-1483-1-ND, TempCo=X7R, Tolerance_%=10%, Value1=Unknown, Value2=50V, ValueDisplayed=220pF
C24 C25: library part CMP-0007356-3, "CAP, CERM, 2.2 uF, 35 V, +/- 10%, X5R, 0603", Cap_Case=0603, Manufacturer=MuRata, Supplier Part Number 1=490-7204-6-ND, TempCo=X5R, Tolerance_%=10%, Value1=Unknown, Value2=35V, ValueDisplayed=2.2uF
C26: library part CMP-0007129-3, "CAP, CERM, 68 pF, 50 V, +/- 5%, C0G/NP0, AEC-Q200 Grade 1, 0603", Cap_Case=0603, Manufacturer=MuRata, Supplier Part Number 1=490-4961-1-ND, TempCo=C0G/NP0, Tolerance_%=5%, Value1=Unknown, Value2=50V, ValueDisplayed=68pF
C28 C29 C30 C31: library part CMP-0084048-1, "CAP, CERM, 0.022 µF, 1000 V,+/- 10%, X7R, AEC-Q200 Grade 1, 1206", Cap_Case=1206, Manufacturer=Kemet, TempCo=X7R, Tolerance_%=10%, Value2=1000V, ValueDisplayed=0.022µF
C32 C33 C34 C35: library part CMP-0009326-2, "CAP, CERM, 0.1 uF, 1000 V, +/- 10%, X7R, 1812", Cap_Case=1812, Manufacturer=Kemet, Supplier Part Number 1=399-6523-1-ND, TempCo=X7R, Tolerance_%=10%, Value1=Unknown, Value2=1000V, ValueDisplayed=0.1uF
D1: library part CMP-0093179-1, "Rectifier Diode Schottky 200V 1A 2-Pin SOD-123HE T/R", Digikey Part Number=SS1H20LSRVGCT-ND, Forward Current=1A, Manufacturer="Taiwan Semiconductor", Max Surge Forward Current=30A, Mouser Part Number=821-SS1H20LSRVG, Operating Temperature Range="-55°C to +150°C", Peak Reverse Current=1uA
D2: library part CMP-0076882-1, "Diode, Ultrafast, 1000 V, 1 A, SMA", Manufacturer="Diodes Inc.", Supplier Part Number 1=US1M-FDICT-ND, Value1=1A, Value2=1.7V
D4 D5: library part CMP-0005769-2, "Diode, Zener, 18 V, 500 mW, AEC-Q101, SOD-123", Manufacturer="Diodes Inc.", Power_W=500mW, Supplier Part Number 1=BZT52C18-FDICT-ND, Value1=0.5W
J2: library part CMP-0095158-1, Digikey Part Number=TSM-107-03-L-SV-ND, Manufacturer=Samtec, Mouser Part Number=200-TSM10703LSV, Operating Temperature Range="-55°C to +125°C"
L1 L2: library part CMP-0058910-1, "Inductor, Shielded, Metal Composite, 4.7 uH, 1.2 A, 0.25 ohm, SMD", Manufacturer="MuRata Toko", PartNumber=1269AS-H-4R7M{}P2, Value1="0.25 ohm", Value2=1.2A, ValueDisplayed=4.7uH
MP1 MP4 MP7: library part CMP-0095159-2, "1 Pin Screw Terminal, Power Tap M3, 6mm, Surface Mount", Manufacturer="Wurth Electronics", Operating Temperature Range=to
MP3 MP6 MP8 MP9: library part CMP-0097508-1, Manufacturer="Wurth Electronics", Operating Temperature Range="-55°C to +150°C"
R1 R2 R12 R13: library part CMP-0027004-2, "RES, 0, 5%, 0.063 W, 0402", Manufacturer="Yageo America", Power_W=63mW, Supplier Part Number 1=311-0.0JRCT-ND, TempCo="200 ppm/C", Tolerance_%=5%, Value2=0.063W, Value_Code=0000, ValueDisplayed=0
R3 R17: library part CMP-0023169-5, "RES, 51.0, 1%, 0.1 W, 0603", Manufacturer=Yageo, Power_W=100mW, Supplier Part Number 1=311-51.0HRCT-ND, TempCo="100 ppm/C", Tolerance_%=1%, Value2=0.1W, Value_Code=51R0, ValueDisplayed=51.0
R4: library part CMP-0022736-4, "RES, 100, 1%, 0.1 W, 0603", Manufacturer=Yageo, Power_W=100mW, Supplier Part Number 1=311-100HRCT-ND, TempCo="100 ppm/C", Tolerance_%=1%, Value2=0.1W, Value_Code=100R, ValueDisplayed=100
R5: library part CMP-0023164-4, "RES, 511 k, 1%, 0.1 W, 0603", Manufacturer=Yageo, Power_W=100mW, Supplier Part Number 1=311-511KHRCT-ND, TempCo="100 ppm/C", Tolerance_%=1%, Value2=0.1W, Value_Code=511k
R6 R7: library part CMP-0022735-5, "RES, 100 k, 1%, 0.1 W, 0603", Manufacturer=Yageo, Power_W=100mW, Supplier Part Number 1=311-100KHRCT-ND, TempCo="100 ppm/C", Tolerance_%=1%, Value2=0.1W, Value_Code=100k
R8: library part CMP-0022923-5, "RES, 22.1 k, 1%, 0.1 W, 0603", Manufacturer=Yageo, Power_W=100mW, Supplier Part Number 1=311-22.1KHRCT-ND, TempCo="100 ppm/C", Tolerance_%=1%, Value2=0.1W, Value_Code=22k1, ValueDisplayed=22.1k
R9 R10 R20: library part CMP-0023013-5, "RES, 300, 1%, 0.1 W, 0603", Manufacturer=Yageo, Power_W=100mW, Supplier Part Number 1=311-300HRCT-ND, TempCo="100 ppm/C", Tolerance_%=1%, Value2=0.1W, Value_Code=300R, ValueDisplayed=300
R11 R21: library part CMP-0023000-5, "RES, 2.00 k, 1%, 0.1 W, 0603", Manufacturer=Yageo, Power_W=100mW, Supplier Part Number 1=311-2.00KHRCT-ND, TempCo="100 ppm/C", Tolerance_%=1%, Value2=0.1W, Value_Code=2k00, ValueDisplayed=2.00k
R14 R15: library part CMP-0022906-5, "RES, 20.0 k, 1%, 0.1 W, 0603", Manufacturer=Yageo, Power_W=100mW, Supplier Part Number 1=311-20.0KHRCT-ND, TempCo="100 ppm/C", Tolerance_%=1%, Value2=0.1W, Value_Code=20k0, ValueDisplayed=20.0k
R16 R19: library part CMP-0022895-5, "RES, 1.00 k, 1%, 0.1 W, 0603", Manufacturer=Yageo, Power_W=100mW, Supplier Part Number 1=311-1.00KHRCT-ND, TempCo="100 ppm/C", Tolerance_%=1%, Value2=0.1W, Value_Code=1k00, ValueDisplayed=1.00k
R18: library part CMP-0017851-1, "RES, 10.0, 1%, 0.25 W, 1206", Manufacturer="Yageo America", Power_W=250mW, Supplier Part Number 1=311-10.0FRCT-ND, TempCo="200 ppm/C", Tolerance_%=1%, Value2=0.25W, Value_Code=10R0, ValueDisplayed=10.0
T1: library part CMP-0095161-1, "Transformer, 1:5, 1500VAC, 10uH, 14x10x5mm", Frequency_Fixed=350kHz, Manufacturer="Wurth Electronics", Operating Temperature Range="-40°C to +125°C", Voltage_Isolation_Vrms=1.5kV
U1: library part CMP-0013278-3, "4.5-V to 28-V Input, 3-A Output Synchronous Step-Down Converter, DDC0006A (SOT-6)", Alternate Manufacturer="Texas Instruments", Alternate PartNumber=TPS54308DDCT
U2: library part CMP-0089949-1, "Low Speed, General Purpose, Robust EMC, Dual-Channel Digital Isolators", Manufacturer="Texas Instruments", Max Supply Voltage=5.5V, Min Supply Voltage=1.71V, Operating Temperature Range="to +150°C"
U3 U4: library part CMP-0094891-1, "650-V 30-mΩ GaN FET with Integrated Driver, Protection, and Temperature Reporting", Manufacturer="Texas Instruments", Max Supply Voltage=18V, Min Supply Voltage=7.5V, Nominal Supply Current=16mA, Operating Temperature Range="-40°C to +150°C", Output Voltage=520V
U6: "Single 2-Input Positive-AND Gate, DBV0005A", Alternate Manufacturer="Texas Instruments", Alternate PartNumber=SN74AHC1G08DBVT

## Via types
v1: diameter 0.508, hole 0.254, Top Layer to Bottom Layer, tented both sides, 150 vias
v2: diameter 0.5, hole 0.2, Top Layer to Bottom Layer, 12 vias
v3: diameter 0.864, hole 0.406, Top Layer to Bottom Layer, 5 vias

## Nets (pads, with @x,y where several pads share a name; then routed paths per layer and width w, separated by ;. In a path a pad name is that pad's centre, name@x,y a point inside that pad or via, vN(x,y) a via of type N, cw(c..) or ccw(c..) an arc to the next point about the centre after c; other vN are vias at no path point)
3.3V: C4.1 C5.1 C9.1 C22.1 C36.1 J2.1 R3.2 T1.3 T1.4 U2.1 U6.5 | length 52.3
  Top Layer w0.3: U2.1@27.595,11.25 U2.1@27.645,11.3
  Top Layer w0.5: T1.3@17.35,5.125 22.025,5.125 C22.1@22.65,5.75 22.65,7.65 C4.1@22.7,7.7 24.325,9.325 R3.2@24.594,9.325 26.075,10.806 C9.1@26.075,11.25 U2.1@27.595,11.25 ; U6.5@46.561,10.325 47.725,10.325 C36.1@48.1,10.7 v2(49.3,10.7) 54.75,10.7 55,10.95 C5.1@55.05,10.9 55.05,6.05 J2.1@55,6
  Signal Layer 1 w0.5: v1(25.725,10.425) 26.9,11.6 46.725,11.6 47.625,10.7 v2(49.3,10.7)
5V_H: C10.1 C14.2 R12.1 U2.8 U3.51 | length 13.5
  Top Layer w0.3: C14.2@22.7,21.8 23.151,21.349 23.151,20.954 v1(23.205,20.9) 23.205,20.43 R12.1@22.875,20.1 ; v1@28.046,17.404 29.167,18.525 C10.1@29.2,18.525 ; U2.8@27.645,16.7 28,17.055 v1(28,17.45) 27.645,17.095 U2.8@27.645,16.7
  Signal Layer 1 w0.3: v1(23.205,20.9) 23.205,20.004 23.151,19.949 24.475,18.625 26.825,18.625 v1(28,17.45)
  Bottom Layer w0.3: v1(23.205,20.9) 23.205,21.125 23.215,21.135 U3.51@23.215,22.075
5V_L: C15.2 R13.1 U4.51 | length 4.2
  Top Layer w0.3: R13.1@36.825,19.025 36.825,20.375 C15.2@37,20.55 37.8,20.55 v1(37.901,20.651)
  Signal Layer 1 w0.3: v1@37.901,20.569 v1(37.901,20.651)
  Bottom Layer w0.3: v1(37.901,20.651) 37.901,20.944 38.04,21.082 U4.51@38.04,22.125
15V: C7.1 C8.1 C13.1 D4.1 J2.7 R5.2 R18.1 U1.3 U4.44 | length 43.2
  Top Layer w0.3: U1.3@31.25,4.2 31.25,3.914 31.889,3.275 33.475,3.275 C8.1@34.575,4.375 36.425,4.375 C7.1@36.55,4.5 ; C13.1@41.94,22.075 41.94,21.706 42.71,20.937 v1(42.8,20.937)
  Top Layer w0.5: R5.2@34.6,9.275 38.2,9.275 38.225,9.3 ; C7.1@36.55,4.5 C7.1@36.702,4.5 ; v1(37.232,16.18) 37.566,15.845 37.566,14.4 37.754,14.212 D4.1@38.963,14.212 39.665,13.509 R18.1@39.665,11.4 38.225,9.96 38.225,9.3 ; J2.7@39.78,4.54 39.78,3.715 39.665,3.6 39.629,3.636 37.566,3.636 C7.1@36.702,4.5 ; C7.1@36.702,4.5 36.911,4.5 38.225,5.814 38.225,9.3
  Signal Layer 1 w0.3: v1(37.232,16.18) 37.232,20.857 38.225,21.85 42.05,21.85 42.8,21.1 v1(42.8,20.937)
  Bottom Layer w0.3: U4.44@42.59,22.183 U4.44@42.59,22.075 42.59,21.147 v1(42.8,20.937)
FAULT: J2.5 U6.4 | length 5.9
  Top Layer w0.6: U6.4@44.661,10.325 44.661,4.739 J2.5@44.86,4.54
FLT_H: C2.1 R20.2 U6.1 | length 7.4
  Top Layer w0.3: R20.2@41.5,12.228 C2.1@43.077,10.65 43.1,10.65 44.15,11.7 46.3,11.7 46.561,11.961 U6.1@46.561,13.075
FLT_HS: U2.7 U3.46 | length 6.7
  Top Layer w0.3: U2.7@28.915,16.7 29.25,17.035 v1(29.25,17.4)
  Signal Layer 1 w0.3: v1(26.375,21.125) 26.375,20.275 v1(29.25,17.4)
  Bottom Layer w0.3: v1@26.465,21.125 U3.46@26.465,22.075
FLT_L: R19.1 U4.46 | length 5.4
  Top Layer w0.3: v2(42.06,18.725) 42.06,18.44 42.666,17.835 R19.1@43.293,17.835
  Bottom Layer w0.3: U4.46@41.29,22.075 41.29,19.495 v2(42.06,18.725)
GND: C2.2 C4.2 C5.2 C7.2 C8.2 C9.2 C13.2 C15.1 C16.2 C17.2 C19.2 C22.2 C24.2 C28.2 C29.2 C30.2 C31.2 C32.2 C33.2 C34.2 C35.2 C36.2 D4.2 J2.6 L2.1 MP7.1 R1.1 R4.2 R7.1 R8.1 R11.2 R15.1 R21.1 U1.1 U2.4 U4.18 U4.19 U4.20 U4.21 U4.22 U4.23 U4.24 U4.25 U4.26 U4.28 U4.29 U4.30 U4.31 U4.32 U4.33 U4.34 U4.35 U4.36 U4.37 U4.38 U4.39 U6.3 | length 112.1
  Top Layer w0.3: v1(21.75,4.125) 22.625,4.125 C22.2@22.65,4.15 ; C4.2@22.7,11.1 C9.2@24.325,11.1 ; U1.1@29.35,4.2 29.325,4.225 v1(29.325,5.1) 29.331,5.106 32.081,5.106 32.3,4.887 R8.1@32.94,4.375 32.975,4.375 C8.2@34.575,5.975 ; U2.4@31.455,11.3 31.455,10.13 v1(31.425,10.1) C16.2@31.425,9.3 ; R7.1@32.94,9.3 C16.2@31.425,9.3 ; C7.2@36.475,6.4 36.15,6.4 35.725,5.975 C8.2@34.575,5.975 ; C16.2@31.425,9.3 C16.2@31.2,9.075 31.2,8.419 v2(31.7,7.919) 32.01,7.609 32.01,7.16 32.32,6.85 33.535,6.85 34.41,5.975 C8.2@34.575,5.975
  Top Layer w0.45: v2(40.615,15.845) 40.748,15.845 41.004,16.101 R1.1@41.8,16.101
  Top Layer w0.5: v1(22.7,9.978) C4.2@22.7,11.1 ; v1(25.165,6.76) 25.9,6.025 R4.2@25.9,5.875 ; C7.2@36.55,6.532 v2(36.55,7.9) ; C19.2@38.26,17.172 38.26,16.35 38.67,15.94 v2(38.67,15.925) ; v2@39.799,15.901 R15.1@39.799,17.185 ; 40.15,22.4 40.15,21.225 C17.2@41.4,19.974 ; v2(41.2,14.2) 42.226,14.2 D4.2@42.237,14.212 ; C2.2@43.077,12.25 43.077,12.89 v2(43.6,13.413) ; C24.2@43.077,23.927 C24.2@43.1,23.95 C24.2@43.375,23.675 ; 43.199,23.464 43.199,21.975 44.56,20.615 L2.1@45.175,20.615 45.177,20.613 v1(45.177,19.791) ; R21.1@43.726,14.613 43.726,13.538 v2(43.6,13.413) ; U6.3@44.661,13.075 43.938,13.075 v2(43.6,13.413) ; v1(47.522,16.903) 47.543,16.925 R11.2@48.65,16.925 ; v2(48.089,13.59) 48.1,13.579 C36.2@48.1,12.3 ; v3(55.05,12.95) C5.2@55.05,14.3
  Top Layer w1: v3(41.971,3.9) 42.32,4.249 J2.6@42.32,7.46
  Bottom Layer w0.3: 38.06,32.098 38.06,33.648 38.06,35.098 ; 38.69,31.975 U4.19@38.69,33.525 38.69,34.975 ; 39.34,31.975 U4.20@39.34,33.525 39.34,34.975 ; 39.99,31.975 U4.21@39.99,33.525 39.99,34.975 ; 40.64,31.975 U4.22@40.64,33.525 40.64,34.975 ; 41.29,31.975 U4.23@41.29,33.525 MP7.1@41.29,34.975 ; 41.94,31.975 U4.24@41.94,33.525 MP7.1@41.94,34.975 ; 42.59,31.975 U4.25@42.59,33.525 MP7.1@42.59,34.975 ; 43.24,31.975 U4.26@43.24,33.525 MP7.1@43.24,34.975 ; 43.5,24.875 U4.39@45.05,24.875 46.5,24.875 ; 43.5,25.525 U4.38@45.05,25.525 46.5,25.525 ; 43.5,26.175 U4.37@45.05,26.175 46.5,26.175 ; 43.5,26.825 U4.36@45.05,26.825 v1@46.5,26.825 ; 43.5,27.475 U4.35@45.05,27.475 v1@46.5,27.475 ; 43.5,28.125 U4.34@45.05,28.125 v1@46.5,28.125 ; 43.5,28.775 U4.33@45.05,28.775 46.5,28.775 ; 43.5,30.075 U4.31@45.05,30.075 46.5,30.075 ; 43.5,30.725 U4.30@45.05,30.725 v1@46.5,30.725 ; 43.5,31.375 U4.29@45.05,31.375 v1@46.5,31.375 ; 43.5,32.025 U4.28@45.05,32.025 v1@46.5,32.025 ; 43.55,29.4 45.1,29.4 46.55,29.4
  other v1: 37.374,23.322 38.06,23.322 38.746,23.322 39.432,23.322 40.118,23.322 40.803,23.322 41.502,23.351 42.177,23.351 37.374,24.084 38.06,24.084 38.746,24.084 39.432,24.084 40.118,24.084 40.803,24.084 41.489,24.084 42.175,24.084 46.475,27.05 46.984,27.274 46.475,27.575 46.967,27.854 46.475,28.104 46.45,30.95 46.95,31.2 46.45,31.5 46.95,31.775 46.45,32.05 46.028,34.844 46.7,34.886 46.395,35.343 47.005,35.343 46,35.8 46.7,35.8 46.395,36.257 47.005,36.257 46.725,37.3 46.725,38.017 46.725,38.736 46.7,39.457 46.65,40.1 46.647,40.75 47.284,40.75 47.926,40.75
  other v2: 39.8,15.9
